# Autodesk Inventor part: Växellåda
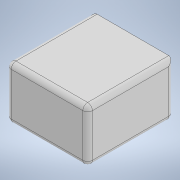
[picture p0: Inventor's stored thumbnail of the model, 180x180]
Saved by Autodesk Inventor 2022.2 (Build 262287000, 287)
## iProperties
Created: 2022-03
Part Number: Växellåda
Material: Generic
Document SubType Name: Modeling
Designer: cl
Density: 1 g/cm^3
Appearance: Default
Author: cl
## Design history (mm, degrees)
sketch "Sketch1"
  geometry: L1 (0, 0)-(170, 0); L2 (170, 0)-(170, -180); L3 (170, -180)-(0, -180); L4 (0, -180)-(0, 0)
  constraints: 8 end point, 2 parallel, 1 horizontal, 1 perpendicular
  dimensions: "d0" = 170 distance of L2.end L3.end; "d1" = 180 distance of L1.end L2.end
extrude "Extrusion1" new body sketch "Sketch1" distance "d2" = 110; taper "d3" = 0 deg
fillet "Fillet1" dims "d4" = 10
body "Solid1"
